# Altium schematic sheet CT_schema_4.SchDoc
size 326 x 334 mm
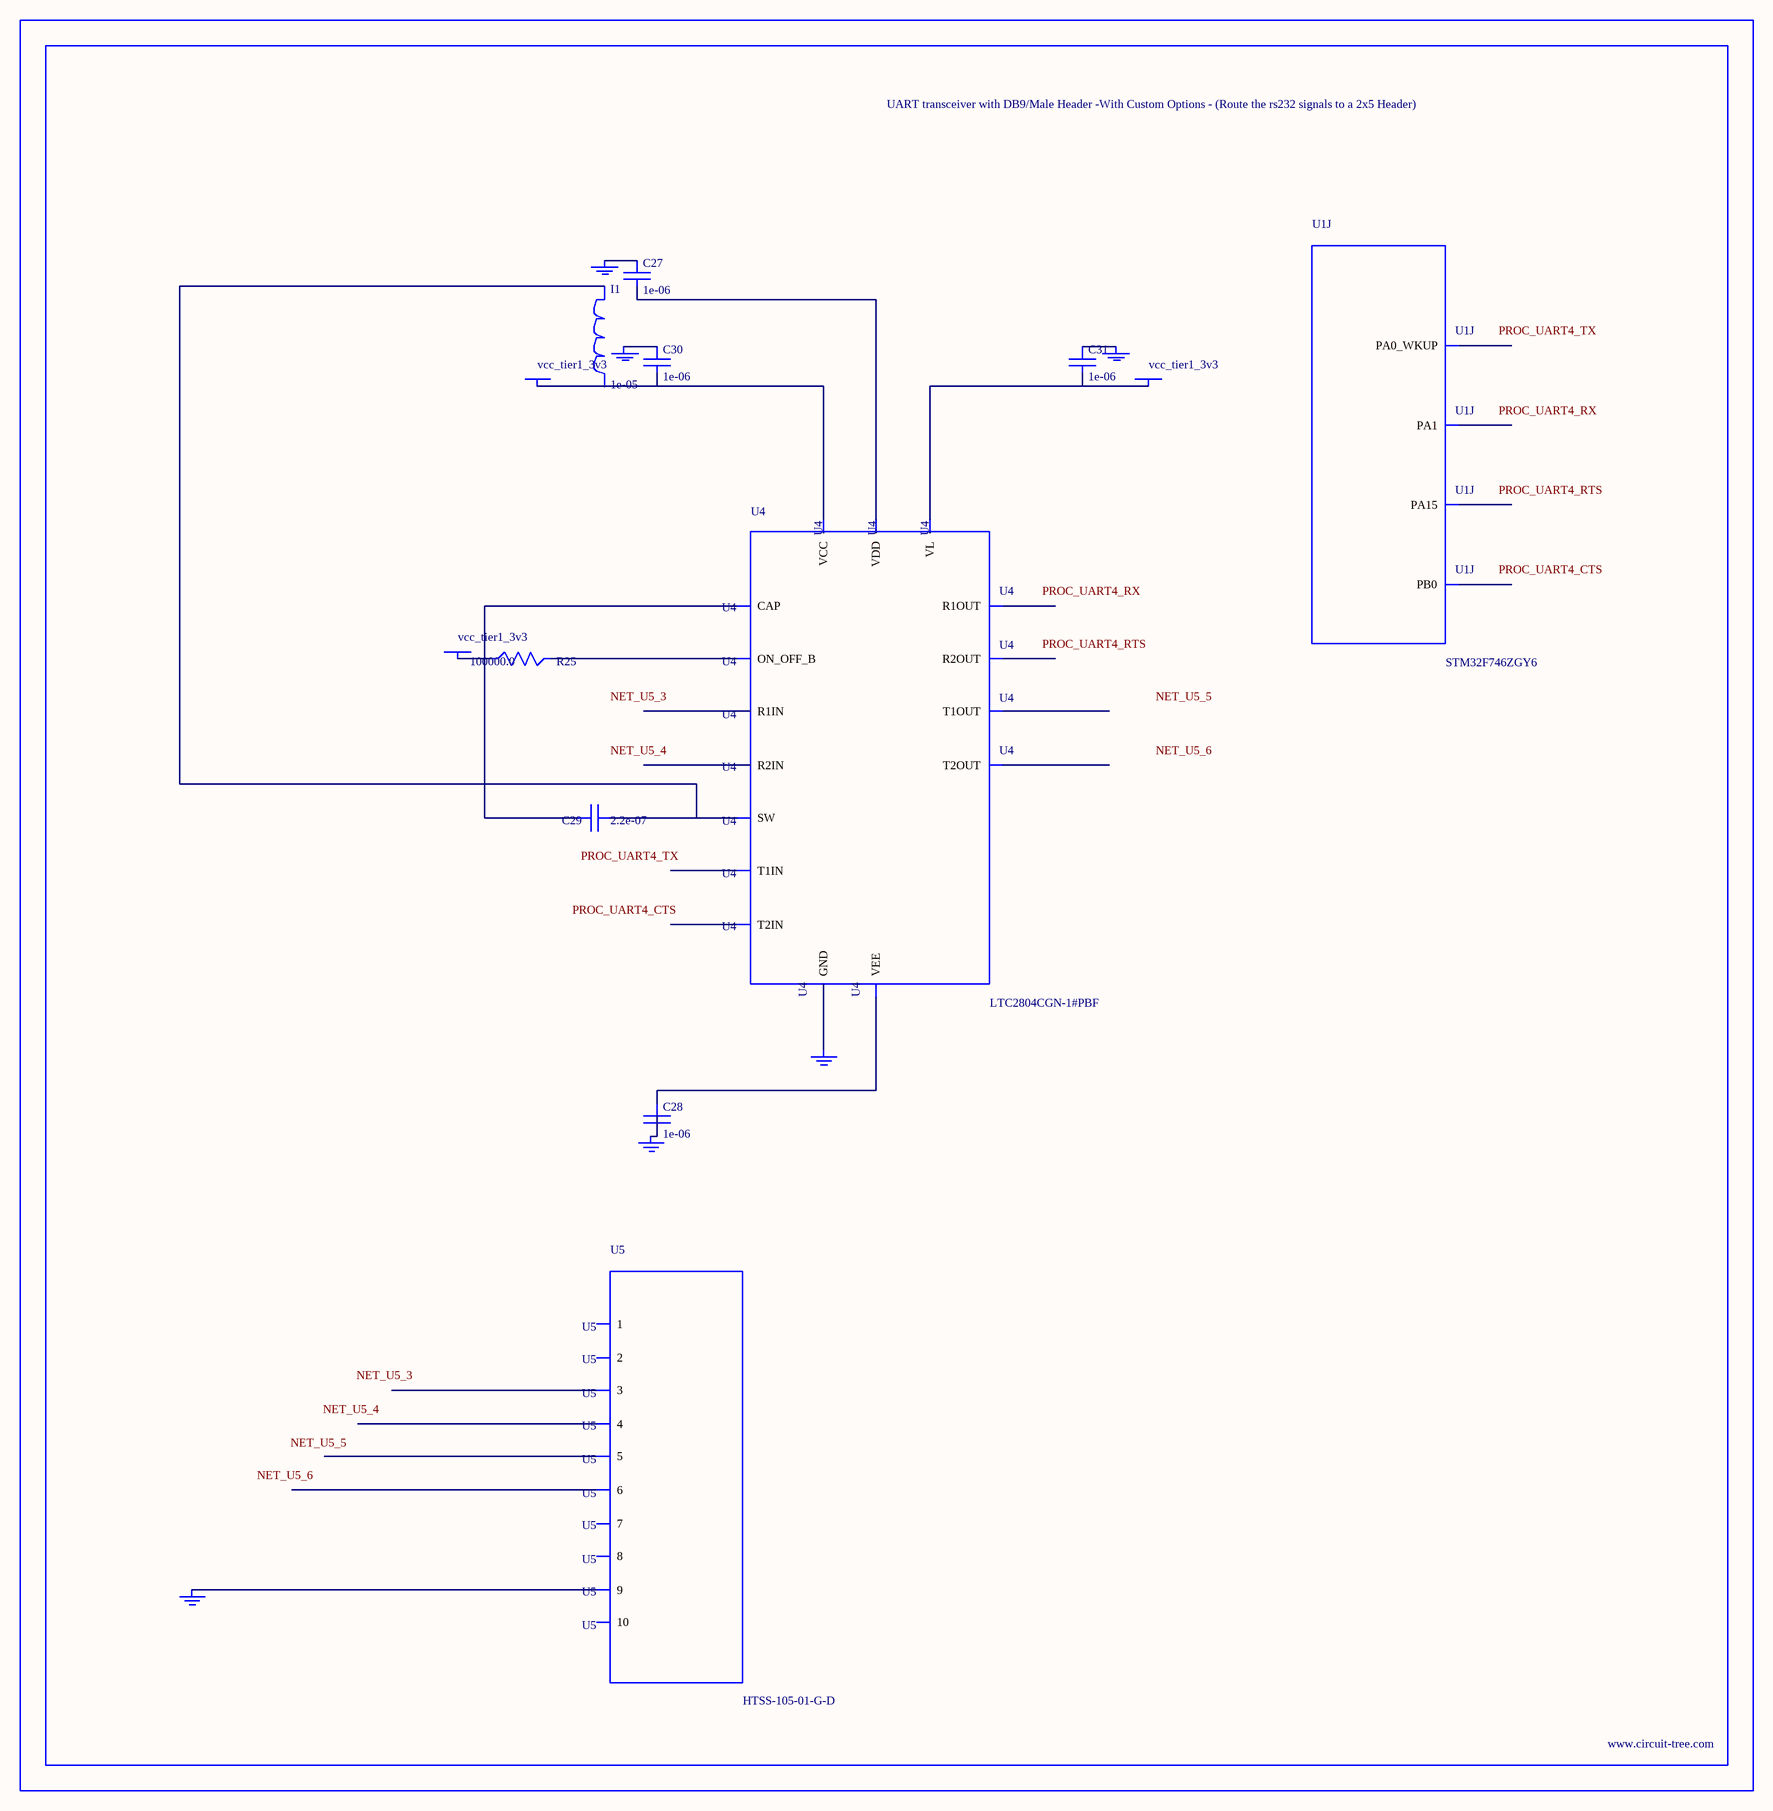
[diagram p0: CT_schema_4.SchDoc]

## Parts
BORDER3  (no value)
C27  1e-06  [C0603]
C28  1e-06  [C0603]
C29  2.2e-07  [C0603]
C30  1e-06  [C0603]
C31  1e-06  [C0603]
GND_INSTANCE_3_0  (no value)
GND_INSTANCE_3_1  (no value)
GND_INSTANCE_3_2  (no value)
GND_INSTANCE_3_3  (no value)
GND_INSTANCE_3_4  (no value)
GND_INSTANCE_3_5  (no value)
I1  1e-05  [L1210]
POWER_INSTANCE_3_0  vcc_tier1_3v3
POWER_INSTANCE_3_1  vcc_tier1_3v3
POWER_INSTANCE_3_2  vcc_tier1_3v3
R25  100000.0  [R0603]
U1  STM32F746ZGY6  [WLCSP143]  (part J of 13)
U4  LTC2804CGN-1#PBF  [SSOP-16]
U5  HTSS-105-01-G-D  [HTSS-105-01-G-D]

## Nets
NetC27_1: C27.1 GND_INSTANCE_3_1.0(GND)
NetC27_2: C27.2 U4.6(VDD)
NetC28_1: C28.1 U4.9(VEE)
NetC28_2: C28.2 GND_INSTANCE_3_2.0(GND)
NetC29_1: C29.1 I1.1 U4.7(SW)
NetC29_2: C29.2 U4.10(CAP)
NetC30_1: C30.1 GND_INSTANCE_3_0.0(GND)
NetC30_2: C30.2 POWER_INSTANCE_3_0.0(PWR) U4.5(VCC)
NetC31_1: C31.1 GND_INSTANCE_3_3.0(GND)
NetC31_2: C31.2 POWER_INSTANCE_3_2.0(PWR) U4.12(VL)
NetGND_INSTANCE_3_4_0: GND_INSTANCE_3_4.0(GND) U4.8(GND)
NetGND_INSTANCE_3_5_0: GND_INSTANCE_3_5.0(GND) U5.9
NetPOWER_INSTANCE_3_1_0: POWER_INSTANCE_3_1.0(PWR) R25.1
NetR25_2: R25.2 U4.11(ON_OFF_B)

Not connected (* = marked no-connect by the designer): I1 2; U1 C2(PA15) K8(PA1) K9(PA0_WKUP) N8(PB0); U4 1(R1IN) 2(R2IN) 3(T1OUT) 4(T2OUT) 13(T2IN) 14(T1IN) 15(R2OUT) 16(R1OUT); U5 1 2 3 4 5 6 7 8 10

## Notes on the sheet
- Labels drawn without touching a wire or pin: NET_U5_3, NET_U5_4, NET_U5_5, NET_U5_6, PROC_UART4_CTS, PROC_UART4_RTS, PROC_UART4_RX, PROC_UART4_TX

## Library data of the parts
BORDER3 = BORDER_PAGE3
C27 C28 C30 C31 = C0603C105K3RACTU
C29 = C0603C224K3RAC
GND_INSTANCE_3_0-GND_INSTANCE_3_5 = GND
I1 = CBC3225T100MR
POWER_INSTANCE_3_0-POWER_INSTANCE_3_2 = PWR
R25 = RC0603JR-07100KL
